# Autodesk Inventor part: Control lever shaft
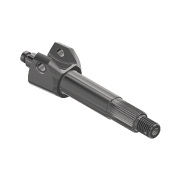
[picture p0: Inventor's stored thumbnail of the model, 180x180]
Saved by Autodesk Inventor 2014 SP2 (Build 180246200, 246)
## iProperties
Created: 2015-03
Part Number: Control lever shaft
Material: Steel
Document SubType Name: Modeling
Designer: SFC
Density: 7.85 g/cm^3
Appearance: Steel - Polished
Author: SFC
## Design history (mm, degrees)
sketch "Sketch1"
  geometry: L1 (-49.589, -6.397)-(49.589, 6.397); L2 (-69.425, 0)-(69.425, 0) reference; 4 further points
  constraints: 2 end point, 2 point on line, 1 coincident, 1 midpoint
  dimensions: "d0" = 100 distance of L1.start L1.end; "d1" = 7.35 deg angle of L1 L2; "d2" = 29.6 distance of point (29.6, 0) point (0, 0); "d3" = 51 distance of point (29.6, 0) point (-21.4, 0)
workplane "Work Plane1"
workplane "Work Plane2"
workplane "Work Plane3"
sketch "Sketch2"
  geometry: L1 (-30, -3.136)-(-25, 30.31); L2 (25, 30.31)-(30, -3.136); L3 (0, -36.658)-(0, 51.948) reference; A1 r 39.29 centre (0, 0) between (25, 30.31) and (-25, 30.31); A2 r 32 centre (0, 8) between (-30, -3.136) and (30, -3.136); 1 further point
  constraints: 4 end point, 4 point on circle, 2 centre point, 1 coincident, 1 vertical alignment, 1 other
  dimensions: "d4" = 39.29 radius of A1; "d5" = 32 radius of A2; "d6" = 8 distance of point (0, 0) A2.centre; "d7" = 50 distance of L2.start L1.end; "d8" = 60 distance of L2.end L1.start
extrude "Extrusion1" new body sketch "Sketch2" stored distance "d9" = 10; taper "d10" = 0 deg
workplane "Work Plane4"
sketch "Sketch3"
  geometry: C1 r 50 at (50, 60); 1 further point
  constraints: 1 centre point, 1 vertical alignment
  dimensions: "d12" = 50 radius of C1; "d13" = 60 distance of point (50, 0) C1.centre
extrude "Extrusion2" cut sketch "Sketch3" stored distance "d14" = 31; taper "d15" = 0 deg
fillet "Fillet1" dims "d16" = 2
sketch "Sketch4"
  geometry: L1 (48.5, 43)-(51.5, 43); L2 (48.5, 0)-(51.5, 0); A1 r 21.5 centre (48.5, 21.5) between (48.5, 43) and (48.5, 0); A2 r 21.5 centre (51.5, 21.5) between (51.5, 0) and (51.5, 43); 2 further points
  constraints: 4 end point, 4 point on circle, 4 tangent, 2 centre point, 1 coincident, 1 equal radius, 1 horizontal alignment, 1 midpoint
  dimensions: "d17" = 21.5 radius of A1; "d18" = 3 distance of A2.centre A1.centre
extrude "Extrusion3" cut sketch "Sketch4" stored distance "d19" = 27.24; taper "d20" = 0 deg
fillet "Fillet2" dims "d21" = 2
sketch "Sketch5"
  geometry: L1 (21.4, 0)-(-29.6, 0); L2 (-29.6, 0)-(-29.6, 23); L3 (-29.6, 23)-(-5.167, 45); L4 (-5.167, 45)-(8.107, 45); L5 (8.107, 45)-(21.4, 20); L6 (21.4, 20)-(21.4, 0); L7 (21.4, 30.31)-(21.4, -3.136) reference; L8 (-29.6, 30.31)-(-29.6, -3.136) reference; 1 further point
  constraints: 12 end point, 2 collinear, 2 parallel, 1 horizontal, 1 perpendicular, 1 point on line
  dimensions: "d22" = 28 deg angle of L5 L6; "d23" = 42 deg angle of L1 L3; "d24" = 90 diameter of L4 L1; "d25" = 40 diameter of L5.end L1; "d26" = 46 diameter of L2.end L1
revolve "Revolution1" sketch "Sketch5" stored, may be unused: angle "d27" = 90 deg
sketch "Sketch6"
  geometry: L1 (-32.5, 23.39)-(-32.5, 32.39); L2 (-32.5, 32.39)-(-25, 32.39); L3 (-25, 32.39)-(-25, 29.39); L4 (-25, 29.39)-(25, 29.39); L5 (25, 29.39)-(25, 32.39); L6 (25, 32.39)-(32.5, 32.39); L7 (32.5, 32.39)-(32.5, 23.39); L8 (32.5, 23.39)-(-32.5, 23.39); 3 further points
  constraints: 16 end point, 5 parallel, 2 collinear, 2 midpoint, 2 vertical alignment, 1 perpendicular, 1 vertical
  dimensions: "d28" = 50 distance of L3.end L4.end; "d29" = 65 distance of L6.end L1.end; "d30" = 23.39 distance from line of point (0, 0) L8; "d31" = 18 diameter of L2 L8; "d32" = 12 diameter of L4 L8
revolve "Revolution2" sketch "Sketch6" stored, may be unused: angle "d33" = 90 deg
sketch "Sketch7"
  geometry: L1 (21.4, 15.52)-(21.4, -20) reference; L2 (-29.6, -23)-(-29.6, 20.523) reference; L3 (53.4, 0)-(53.4, 8); L4 (53.4, 8)-(47.4, 8); L5 (47.4, 8)-(47.4, 5.25); L6 (47.4, 5.25)-(41.4, 5.25); L7 (41.4, 5.25)-(41.4, 10.55); L8 (41.4, 10.55)-(21.4, 10.55); L9 (21.4, 10.55)-(21.4, 0); L10 (21.4, 0)-(53.4, 0); L11 (-29.6, 0)-(-29.6, 16.5); L12 (-29.6, 16.5)-(-113.6, 16.5); L13 (-113.6, 16.5)-(-113.6, 15); L14 (-113.6, 15)-(-160.6, 15); L15 (-160.6, 15)-(-160.6, 11); L16 (-160.6, 11)-(-188.6, 11); L17 (-188.6, 11)-(-188.6, 0); L18 (-188.6, 0)-(-29.6, 0); 3 further points
  constraints: 32 end point, 7 parallel, 6 perpendicular, 5 point on line, 1 collinear, 1 horizontal
  dimensions: "d34" = 21.1 diameter of L8 L10; "d35" = 10.5 diameter of L6 L10; "d36" = 16 diameter of L4 L10; "d37" = 6 distance between parallel lines of L5 L3; "d38" = 6 distance between parallel lines of L7 L5; "d39" = 32 distance between parallel lines of L1 L3; "d40" = 242 distance between parallel lines of L17 L3; "d41" = 47 distance of L13.end L14.end; "d42" = 28 distance of L15.end L16.end; "d43" = 33 diameter of L12 L18; "d44" = 30 diameter of L14 L18; "d45" = 22 diameter of L16 L18
revolve "Revolution3" sketch "Sketch7" stored, may be unused: angle "d46" = 90 deg
fillet "Fillet3" dims "d47" = 1.5
fillet "Fillet4" dims "d48" = 0.5
thread "Thread1" dims "d49" = 24.5, "d50" = 0
chamfer "Chamfer1" distance "d51" = 1.5; stored, may be unused: second distance "d52" = 2, angle "d53" = 45 deg
chamfer "Chamfer2" distance "d54" = 0.5; stored, may be unused: second distance "d55" = 2, angle "d56" = 45 deg
hole "Hole1" diameter "d59" = 6; stored, may be unused: countersink angle "d63" = 60 deg, drill point angle "d65" = 118 deg; dims "d57" = 10, "d58" = 10, "d60" = 6, "d61" = 11, "d62" = 2, "d64" = 11.5
hole "Hole2" diameter "d68" = 3; stored, may be unused: countersink angle "d72" = 60 deg, drill point angle "d74" = 118 deg; dims "d66" = 10, "d67" = 10, "d69" = 6, "d70" = 9, "d71" = 2, "d73" = 10
sketch "Sketch8"
  geometry: L1 (-14.953, -1.185)-(-13.35, -0.26); L2 (-13.35, 0.26)-(-14.953, 1.185); L3 (36.077, 0)-(-48.135, 0) reference; C1 r 12.5 at (0, 0) reference; A1 r 15 centre (0, 0) between (-14.953, -1.185) and (-14.953, 1.185) reference; A2 r 15 centre (0, 0) between (-14.953, -1.185) and (-14.953, 1.185) reference; A3 r 0.3 centre (-13.5, 0) between (-13.35, -0.26) and (-13.35, 0.26)
  constraints: 6 point on circle, 4 end point, 2 tangent, 1 centre point, 1 other
  dimensions: "d75" = 60 deg angle of L2 L1; "d76" = 0.3 radius of A3; "d77" = 13.5 distance of C1.centre A3.centre
extrude "Extrusion4" cut sketch "Sketch8" distance "d78" = 28; taper "d79" = 0 deg
sketch "Sketch9"
  geometry: L1 (-13.35, -0.26)-(-14.953, -1.185) reference; L2 (-14.953, 1.185)-(-13.35, 0.26) reference; L3 (-53, -7.396)-(-53, 6.19); A1 r 0.3 centre (-13.5, 0) between (-13.35, -0.26) and (-13.35, 0.26) reference; A2 r 15 centre (0, 0) between (-14.953, 1.185) and (-14.953, -1.185) reference
  constraints: 2 end point, 1 vertical
  dimensions: "d80" = 53 distance from line of A2.centre L3
revolve "Revolution4" sketch "Sketch9" stored, may be unused: angle "d81" = 90 deg
workpoint "Work Point1"
  workaxis "Work Axis1"
hole "Hole3" diameter "d88" = 5; stored, may be unused: countersink angle "d92" = 60 deg, drill point angle "d94" = 118 deg; dims "d86" = 10, "d87" = 10, "d89" = 6, "d90" = 9, "d91" = 2, "d93" = 10
chamfer "Chamfer3" distance "d95" = 0.5; stored, may be unused: second distance "d96" = 2, angle "d97" = 45 deg
body "Solid1"
pattern_circular "Circular Pattern1" dims angle "d83" = 360 deg
workplane "Work Plane5"
other parameters: "d11" = 90 deg
